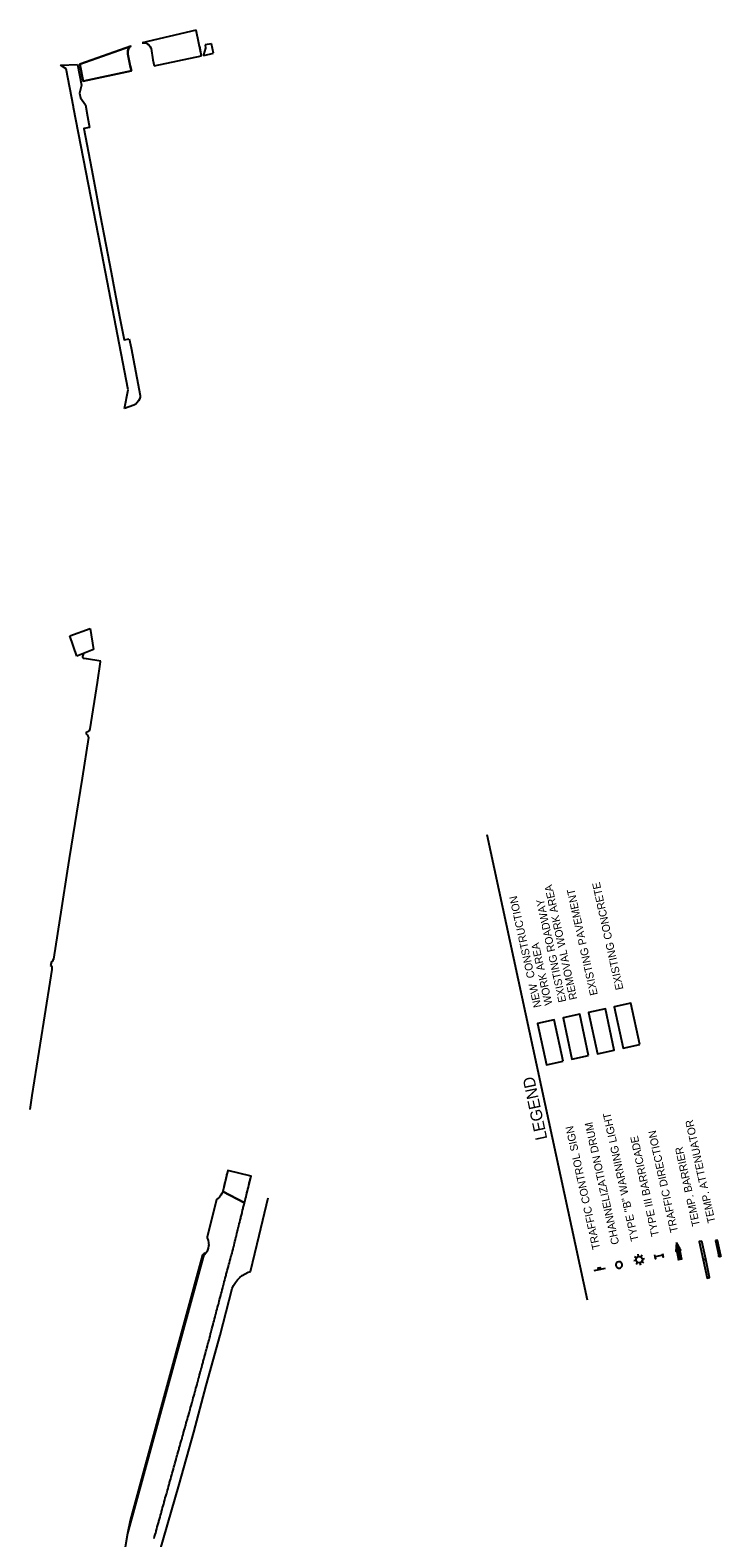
# Model space of a CAD drawing. Extents: x 1795987 to 1799689, y 243690 to 251545.
# Drawn here: x 1798998 to 1799689, y 250036 to 251545 of the extents above; entities that cross this region are included whole.
import ezdxf

# ---------------------------------------------------------------- set-up
doc = ezdxf.new("R2010")
doc.units = 0
for name, color, linetype in [('EP', 7, 'Continuous'), ('LEGEND', 7, 'Continuous'), ('Level 23', 7, 'Continuous'), ('Level 30', 7, 'Continuous'), ('Level 62', 7, 'Continuous')]:
    doc.layers.add(name, color=color, linetype=linetype)

# ---------------------------------------------------------------- blocks, each defined once
blk = doc.blocks.new('T21LR')
at = {"layer": 'Level 23'}
for p, q in [((0, 2), (31.5, 2)), ((0, -2), (31.5, -2))]:
    blk.add_line(p, q, dxfattribs=at)
blk.add_lwpolyline([(0, -2), (4, -2), (4, 2), (0, 2)], close=True, dxfattribs=at)
blk.add_circle((31.5, 0), 2, dxfattribs=at)

msp = doc.modelspace()

# ---------------------------------------------------------------- linework, layer by layer
at = {"layer": 'EP'}
for p, q in [((1799167.6, 251528.7), (1799169.5, 251519)), ((1799179.8, 251531.2), (1799173.2, 251529.9)), ((1799028.5, 251509.8), (1799045.8, 251510.4)), ((1799059.6, 251406.2), (1799063.9, 251383.2)), ((1799092.6, 251166.3), (1799096.4, 251184.9)), ((1799065.5, 250892), (1799068.8, 250912.7)), ((1799068.9, 250913.4), (1799069, 250913.4)), ((1799035.8, 250703.5), (1799037.8, 250715.9)), ((1799019.6, 250612.8), (1799018.8, 250608.9)), ((1798998.3, 250465.1), (1799000.3, 250479.1))]:
    msp.add_line(p, q, dxfattribs=at)
for points in [[(1799041.6, 251468.2), (1799034.2, 251506.1), (1799028.5, 251509.8)], [(1799045.8, 251510.4), (1799049.6, 251489.8), (1799047.5, 251481.7), (1799048.6, 251476.9), (1799053.5, 251469.9), (1799055.6, 251458.3), (1799057.7, 251447.2)], [(1799096.4, 251184.9), (1799066.7, 251339), (1799041.8, 251467.3), (1799041.6, 251468.2)], [(1799057.7, 251447.2), (1799052, 251446.2), (1799059.6, 251406.2)], [(1799063.9, 251383.2), (1799068.4, 251359.7), (1799074, 251330.3), (1799079.3, 251302.7), (1799082.7, 251284.5), (1799088, 251256.7), (1799092.2, 251234.9), (1799097.5, 251235.9)], [(1799097.5, 251235.9), (1799099.3, 251226.8), (1799108.4, 251179.3), (1799108.2, 251177.7), (1799107.6, 251175.7), (1799106.7, 251173.8), (1799105.4, 251172.1), (1799103.9, 251170.6), (1799102.1, 251169.5), (1799092.6, 251166.3)], [(1799069, 250913.4), (1799054.5, 250915.7), (1799052.2, 250916.1), (1799051.7, 250916.3), (1799051.5, 250916.5), (1799051.3, 250916.8), (1799051.1, 250917.6), (1799051.1, 250918.2), (1799051.2, 250919.3), (1799051.9, 250921.1)], [(1799068.8, 250912.7), (1799068.9, 250913.4)], [(1799037.8, 250715.9), (1799050.5, 250796.5), (1799056.9, 250837.1), (1799056.4, 250838.4), (1799055.6, 250839.6), (1799055.4, 250839.8), (1799055.3, 250839.9), (1799054.7, 250840.5), (1799054.5, 250841.3), (1799054.6, 250842.1), (1799055.1, 250842.7), (1799055.9, 250843), (1799056.1, 250843), (1799056.2, 250843), (1799057.2, 250843.8), (1799058, 250844.8), (1799058.3, 250845.8), (1799065.5, 250892)], [(1799019.6, 250612.8), (1799020.7, 250613.4), (1799021.4, 250614.3), (1799021.8, 250615.4), (1799021.9, 250615.5), (1799029.9, 250666.7), (1799035.8, 250703.5)], [(1799000.3, 250479.1), (1799012, 250552.2), (1799020.3, 250605.1), (1799020.4, 250606.2), (1799020.2, 250607.3), (1799019.6, 250608.3), (1799018.8, 250608.9)], [(1799122.3, 250035.8), (1799122.8, 250037.8), (1799123.4, 250039.7), (1799123.9, 250041.6), (1799124.3, 250042.9), (1799124.4, 250043.6), (1799125, 250045.5), (1799125.5, 250047.4), (1799126, 250049.3), (1799126.6, 250051.3), (1799126.9, 250052.6), (1799127.1, 250053.2), (1799127.6, 250055.1), (1799128.2, 250057), (1799128.7, 250059), (1799129.2, 250060.9), (1799129.6, 250062.2), (1799129.8, 250062.8), (1799130.3, 250064.8), (1799130.8, 250066.7), (1799131.4, 250068.6), (1799131.9, 250070.5), (1799132.3, 250071.9), (1799132.5, 250072.5), (1799133, 250074.4), (1799133.5, 250076.3), (1799134.1, 250078.2), (1799134.6, 250080.2), (1799135, 250081.5), (1799135.2, 250082.1), (1799135.7, 250084), (1799136.2, 250085.9), (1799136.8, 250087.9), (1799137.3, 250089.8), (1799137.7, 250091.1), (1799137.8, 250091.7), (1799138.4, 250093.7), (1799138.9, 250095.6), (1799139.5, 250097.5), (1799140, 250099.4), (1799140.4, 250101), (1799141.1, 250103.3), (1799141.6, 250105.2), (1799141.8, 250105.8), (1799142.1, 250107.1), (1799142.7, 250109.1), (1799143.1, 250110.6), (1799143.8, 250112.9), (1799144.3, 250114.8), (1799144.5, 250115.4), (1799144.8, 250116.8), (1799145.4, 250118.7), (1799145.8, 250120.3), (1799146.5, 250122.5), (1799147, 250124.5), (1799147.2, 250125.1), (1799147.5, 250126.4), (1799148.1, 250128.3), (1799148.5, 250129.9), (1799149.1, 250132.2), (1799149.7, 250134.1), (1799149.9, 250134.7), (1799150.2, 250136), (1799150.8, 250138), (1799151.2, 250139.5), (1799151.8, 250141.8), (1799152.4, 250143.7), (1799152.5, 250144.3), (1799152.9, 250145.7), (1799153.5, 250147.6), (1799153.9, 250149.1), (1799154.5, 250151.4), (1799155.1, 250153.4), (1799155.2, 250154), (1799155.6, 250155.3), (1799156.1, 250157.2), (1799156.6, 250158.8), (1799157.2, 250161.1), (1799157.8, 250163), (1799157.9, 250163.6), (1799158.3, 250164.9), (1799158.8, 250166.8), (1799159.3, 250168.4), (1799159.9, 250170.7), (1799160.4, 250172.6), (1799160.6, 250173.2), (1799161, 250174.6), (1799161.5, 250176.5), (1799161.9, 250178.1), (1799162.6, 250180.3), (1799163.1, 250182.3), (1799163.3, 250182.9), (1799163.6, 250184.2), (1799164.1, 250186.1), (1799164.6, 250187.7), (1799165.2, 250190), (1799165.7, 250191.9), (1799165.9, 250192.5), (1799166.3, 250193.8), (1799166.8, 250195.8), (1799167.2, 250197.3), (1799167.8, 250199.6), (1799168.4, 250201.6), (1799168.5, 250202.2), (1799168.9, 250203.5), (1799169.4, 250205.4), (1799169.9, 250207), (1799170.5, 250209.3), (1799171, 250211.2), (1799171.2, 250211.8), (1799171.5, 250213.1), (1799172, 250215.1), (1799172.5, 250216.6), (1799173.1, 250218.9), (1799173.6, 250220.9), (1799173.7, 250221.5), (1799174.1, 250222.8), (1799174.6, 250224.7), (1799175, 250226.3), (1799175.6, 250228.6), (1799176.1, 250230.5), (1799176.3, 250231.1), (1799176.6, 250232.5), (1799177.2, 250234.4), (1799177.6, 250236), (1799178.2, 250238.3), (1799178.7, 250240.2), (1799178.8, 250240.8), (1799179.2, 250242.1), (1799179.7, 250244.1), (1799180.1, 250245.6), (1799180.7, 250247.9), (1799181.2, 250249.9), (1799181.4, 250250.5), (1799181.8, 250251.8), (1799182.3, 250253.7), (1799182.7, 250255.4), (1799183.3, 250257.6), (1799183.8, 250259.5), (1799184, 250260.3), (1799184.3, 250261.5), (1799184.8, 250263.4), (1799185.3, 250265.1), (1799185.8, 250267.3), (1799186.4, 250269.2), (1799186.6, 250269.9), (1799186.9, 250271.1), (1799187.4, 250273.1), (1799187.8, 250274.8), (1799188.4, 250276.9), (1799188.9, 250278.9), (1799189.1, 250279.6), (1799189.4, 250280.8), (1799189.9, 250282.7), (1799190.4, 250284.4), (1799191, 250286.6), (1799191.5, 250288.5), (1799191.7, 250289.3), (1799192, 250290.5), (1799192.5, 250292.4), (1799192.9, 250294.1), (1799193.5, 250296.3), (1799194, 250298.2), (1799194.2, 250298.9), (1799194.5, 250300.1), (1799195.1, 250302.1), (1799195.5, 250303.8), (1799196.1, 250305.9), (1799196.6, 250307.9), (1799196.8, 250308.6), (1799197.1, 250309.8), (1799197.6, 250311.7), (1799198.1, 250313.4), (1799198.6, 250315.6), (1799199.1, 250317.5), (1799199.3, 250318.3), (1799199.7, 250319.5), (1799200.2, 250321.4), (1799200.6, 250323.1), (1799201.2, 250325.3), (1799201.7, 250327.2), (1799201.9, 250327.9), (1799202.2, 250329.2), (1799202.7, 250331.1), (1799203.1, 250332.8), (1799203.6, 250335), (1799204.1, 250336.9), (1799204.3, 250337.6), (1799204.6, 250338.9), (1799205.1, 250340.8), (1799205.5, 250342.5), (1799206, 250344.7), (1799206.5, 250346.6), (1799206.7, 250347.4), (1799207, 250348.6), (1799207.5, 250350.5), (1799207.9, 250352.2), (1799208.4, 250354.4), (1799208.9, 250356.3), (1799209.1, 250357.1), (1799209.4, 250358.3), (1799209.9, 250360.2), (1799210.3, 250361.9), (1799210.8, 250364.1), (1799211.3, 250366), (1799211.5, 250366.8), (1799211.8, 250368), (1799212.3, 250369.9), (1799212.7, 250371.6), (1799219.3, 250398.3), (1799196, 250404), (1799190.9, 250382.9), (1799190.1, 250380.9), (1799189, 250379.1), (1799188.3, 250378.2), (1799187.6, 250377.4), (1799186, 250375.8), (1799184.6, 250374.8), (1799175.2, 250337.4), (1799175.5, 250336.7), (1799176.4, 250333.9), (1799176.8, 250332), (1799176.8, 250331), (1799176.9, 250329.6), (1799176.8, 250328.5), (1799176.3, 250326.3), (1799175.6, 250324.2), (1799174.9, 250322.7), (1799173.1, 250319.9), (1799173.2, 250321.4), (1799172.5, 250320.9), (1799095.7, 250040.7), (1799091, 250013.3)], [(1799218.6, 250302.9), (1799227.2, 250339), (1799236.5, 250376.7)], [(1799124, 250009.1), (1799147.2, 250089.9), (1799161.9, 250142), (1799174.5, 250188.9), (1799188.2, 250239.3), (1799200.5, 250285.8), (1799201.8, 250288.9), (1799203.6, 250291.8), (1799205.6, 250294.4), (1799207.9, 250296.8), (1799210.5, 250298.9), (1799213.4, 250300.7), (1799216.4, 250302.1), (1799218.6, 250302.9)]]:
    msp.add_lwpolyline(points, dxfattribs=at)
at = {"layer": 'LEGEND'}
for p, q in [((1799555.6, 250274.2), (1799455.4, 250739.6)), ((1799606.8, 250317.8), (1799606.3, 250320.1)), ((1799644.9, 250332), (1799644.2, 250323)), ((1799644.2, 250323), (1799645.1, 250323.2)), ((1799649.1, 250324), (1799644.9, 250332)), ((1799645.1, 250323.2), (1799646.9, 250314.3)), ((1799648.2, 250323.8), (1799649.1, 250324)), ((1799650, 250314.9), (1799648.2, 250323.8)), ((1799573.5, 250306), (1799562.1, 250303.5)), ((1799604.3, 250314), (1799602.1, 250313.6)), ((1799604.8, 250316.5), (1799602.8, 250317.7)), ((1799604.5, 250310.1), (1799605.7, 250312)), ((1799608.1, 250311.6), (1799608.6, 250309.3)), ((1799610.4, 250319.3), (1799609.2, 250317.4)), ((1799612.1, 250311.7), (1799610.1, 250313)), ((1799610.6, 250315.4), (1799612.8, 250315.9))]:
    msp.add_line(p, q, dxfattribs=at)
for points in [[(1799582.5, 250524.4), (1799573.6, 250565.7), (1799556.9, 250562.1), (1799565.8, 250520.8)], [(1799608.1, 250529.9), (1799599.2, 250571.2), (1799582.5, 250567.7), (1799591.4, 250526.3)], [(1799531.3, 250513.4), (1799522.4, 250554.7), (1799505.7, 250551.1), (1799514.7, 250509.8)], [(1799556.9, 250518.9), (1799548, 250560.2), (1799531.3, 250556.6), (1799540.2, 250515.3)], [(1799670, 250333.4), (1799667.6, 250332.9), (1799671.5, 250314.6), (1799674, 250315.1)], [(1799566.9, 250304.6), (1799566.5, 250306.5), (1799568.4, 250306.9), (1799568.8, 250305)], [(1799674, 250315.1), (1799671.5, 250314.6), (1799675.5, 250296.2), (1799677.9, 250296.8)]]:
    msp.add_lwpolyline(points, close=True, dxfattribs=at)
for points in [[(1799630.7, 250321), (1799631.4, 250317.2), (1799631, 250319.1), (1799623.4, 250317.6), (1799623.8, 250315.7), (1799623, 250319.5)], [(1799644.2, 250323.2), (1799644.3, 250323)], [(1799644.3, 250324.1), (1799644.5, 250323)], [(1799644.4, 250326), (1799645, 250323.1)], [(1799644.4, 250325.1), (1799644.8, 250323.1)], [(1799644.5, 250326.9), (1799647.1, 250314.3)], [(1799644.6, 250327.9), (1799647.3, 250314.3)], [(1799644.7, 250328.8), (1799647.6, 250314.4)], [(1799644.8, 250330.7), (1799648.1, 250314.5)], [(1799644.8, 250329.7), (1799647.8, 250314.4)], [(1799644.9, 250331.6), (1799648.3, 250314.5)], [(1799645.2, 250331.4), (1799648.6, 250314.6)], [(1799645.6, 250330.6), (1799648.9, 250314.7)], [(1799646.1, 250329.8), (1799649.1, 250314.7)], [(1799646.5, 250328.9), (1799649.4, 250314.8)], [(1799646.9, 250328.1), (1799649.6, 250314.8)], [(1799647.4, 250327.3), (1799649.9, 250314.9)], [(1799647.8, 250326.5), (1799648.3, 250323.8)], [(1799648.2, 250325.6), (1799648.6, 250323.9)], [(1799648.7, 250324.8), (1799648.8, 250323.9)]]:
    msp.add_lwpolyline(points, dxfattribs=at)
msp.add_circle((1799607.5, 250314.7), 3.19, dxfattribs=at)
for start, end in [(102.1577, 282.1577), (282.1577, 102.1577)]:
    msp.add_arc((1799587.3, 250309.5), 3.18, start, end, dxfattribs=at)
at = {"layer": 'Level 30'}
for p, q in [((1799179.8, 251531.2), (1799173.2, 251529.9)), ((1799181.6, 251521.6), (1799179.8, 251531.2))]:
    msp.add_line(p, q, dxfattribs=at)
msp.add_lwpolyline([(1799173.2, 251529.9), (1799173.8, 251526.6), (1799171.8, 251520.1), (1799171.9, 251519.5), (1799181.6, 251521.6)], dxfattribs=at)
at = {"layer": 'Level 62'}
for p, q in [((1799164.2, 251544.8), (1799110.4, 251532.2)), ((1799048.1, 251510.8), (1799099, 251528.6)), ((1799122.4, 251508.9), (1799169.6, 251519)), ((1799038, 250938.8), (1799058.2, 250946.1)), ((1799045, 250918.4), (1799038, 250938.8)), ((1799058.2, 250946.1), (1799061.5, 250925)), ((1799061.5, 250925), (1799045, 250918.4)), ((1799190.9, 250382.9), (1799212.7, 250371.6)), ((1799173.2, 250321.4), (1799173.1, 250319.9))]:
    msp.add_line(p, q, dxfattribs=at)
for points in [[(1799169.6, 251519), (1799167, 251531.6), (1799164.2, 251544.8)], [(1799099.7, 251504), (1799098.5, 251508.9), (1799096, 251520.7), (1799095.9, 251522.5), (1799096.1, 251524.2), (1799096.7, 251525.9), (1799097.7, 251527.4), (1799099, 251528.6), (1799048.1, 251510.8), (1799051.3, 251493.6), (1799099.7, 251504)], [(1799099, 251528.6), (1799097.7, 251527.4), (1799096.7, 251525.9), (1799096.1, 251524.2), (1799095.9, 251522.5), (1799096, 251520.7), (1799098.5, 251508.9), (1799099.7, 251504)], [(1799110.4, 251532.2), (1799112.2, 251532.2), (1799113.9, 251531.9), (1799115.5, 251531.2), (1799117, 251530.1), (1799118.1, 251528.8), (1799118.9, 251527.2), (1799119.2, 251526.3), (1799121.1, 251515.2), (1799122.4, 251508.9)], [(1799099.7, 251504), (1799051.3, 251493.6), (1799048.1, 251510.8)], [(1799565.8, 250520.8), (1799582.5, 250524.4), (1799573.6, 250565.7), (1799556.9, 250562.1), (1799565.8, 250520.8)], [(1799219, 250397.1), (1799219.3, 250398.3), (1799196, 250404), (1799195.6, 250402.5), (1799195.2, 250401.2), (1799195.1, 250400.5), (1799194.8, 250399.5), (1799194.6, 250398.6), (1799194.2, 250396.9), (1799194.1, 250396.7), (1799193.9, 250395.8), (1799193.7, 250394.7), (1799193.6, 250394.4), (1799193.2, 250392.8), (1799193.2, 250392.8), (1799192.7, 250390.8), (1799192.7, 250390.7), (1799192.2, 250388.9), (1799192.1, 250387.9), (1799192, 250387.4), (1799191.4, 250384.3), (1799190.9, 250382.9), (1799212.7, 250371.6), (1799212.7, 250371.9), (1799213.2, 250373.8), (1799213.7, 250375.8), (1799213.9, 250376.5), (1799214.2, 250377.7), (1799214.7, 250379.6), (1799215.1, 250381.3), (1799215.1, 250381.6), (1799215.6, 250383.5), (1799216.1, 250385.5), (1799216.3, 250386.2), (1799216.6, 250387.4), (1799217.1, 250389.3), (1799217.5, 250391), (1799217.5, 250391.3), (1799218, 250393.2), (1799218.2, 250394.1), (1799218.5, 250395.2), (1799218.7, 250395.9), (1799219, 250397.1)], [(1799122.3, 250035.8), (1799122.8, 250037.8), (1799123.4, 250039.7), (1799123.9, 250041.6), (1799124.3, 250042.9), (1799124.4, 250043.6), (1799125, 250045.5), (1799125.5, 250047.4), (1799126, 250049.3), (1799126.6, 250051.3), (1799126.9, 250052.6), (1799127.1, 250053.2), (1799127.6, 250055.1), (1799128.2, 250057), (1799128.7, 250059), (1799129.2, 250060.9), (1799129.6, 250062.2), (1799129.8, 250062.8), (1799130.3, 250064.8), (1799130.8, 250066.7), (1799131.4, 250068.6), (1799131.9, 250070.5), (1799132.3, 250071.9), (1799132.5, 250072.5), (1799133, 250074.4), (1799133.5, 250076.3), (1799134.1, 250078.2), (1799134.6, 250080.2), (1799135, 250081.5), (1799135.2, 250082.1), (1799135.7, 250084), (1799136.2, 250085.9), (1799136.8, 250087.9), (1799137.3, 250089.8), (1799137.7, 250091.1), (1799137.8, 250091.7), (1799138.4, 250093.7), (1799138.9, 250095.6), (1799139.5, 250097.5), (1799140, 250099.4), (1799140.4, 250101), (1799141.1, 250103.3), (1799141.6, 250105.2), (1799141.8, 250105.8), (1799142.1, 250107.1), (1799142.7, 250109.1), (1799143.1, 250110.6), (1799143.8, 250112.9), (1799144.3, 250114.8), (1799144.5, 250115.4), (1799144.8, 250116.8), (1799145.4, 250118.7), (1799145.8, 250120.3), (1799146.5, 250122.5), (1799147, 250124.5), (1799147.2, 250125.1), (1799147.5, 250126.4), (1799148.1, 250128.3), (1799148.5, 250129.9), (1799149.1, 250132.2), (1799149.7, 250134.1), (1799149.9, 250134.7), (1799150.2, 250136), (1799150.8, 250138), (1799151.2, 250139.5), (1799151.8, 250141.8), (1799152.4, 250143.7), (1799152.5, 250144.3), (1799152.9, 250145.7), (1799153.5, 250147.6), (1799153.9, 250149.1), (1799154.5, 250151.4), (1799155.1, 250153.4), (1799155.2, 250154), (1799155.6, 250155.3), (1799156.1, 250157.2), (1799156.6, 250158.8), (1799157.2, 250161.1), (1799157.8, 250163), (1799157.9, 250163.6), (1799158.3, 250164.9), (1799158.8, 250166.8), (1799159.3, 250168.4), (1799159.9, 250170.7), (1799160.4, 250172.6), (1799160.6, 250173.2), (1799161, 250174.6), (1799161.5, 250176.5), (1799161.9, 250178.1), (1799162.6, 250180.3), (1799163.1, 250182.3), (1799163.3, 250182.9), (1799163.6, 250184.2), (1799164.1, 250186.1), (1799164.6, 250187.7), (1799165.2, 250190), (1799165.7, 250191.9), (1799165.9, 250192.5), (1799166.3, 250193.8), (1799166.8, 250195.8), (1799167.2, 250197.3), (1799167.8, 250199.6), (1799168.4, 250201.6), (1799168.5, 250202.2), (1799168.9, 250203.5), (1799169.4, 250205.4), (1799169.9, 250207), (1799170.5, 250209.3), (1799171, 250211.2), (1799171.2, 250211.8), (1799171.5, 250213.1), (1799172, 250215.1), (1799172.5, 250216.6), (1799173.1, 250218.9), (1799173.6, 250220.9), (1799173.7, 250221.5), (1799174.1, 250222.8), (1799174.6, 250224.7), (1799175, 250226.3), (1799175.6, 250228.6), (1799176.1, 250230.5), (1799176.3, 250231.1), (1799176.6, 250232.5), (1799177.2, 250234.4), (1799177.6, 250236), (1799178.2, 250238.3), (1799178.7, 250240.2), (1799178.8, 250240.8), (1799179.2, 250242.1), (1799179.7, 250244.1), (1799180.1, 250245.6), (1799180.7, 250247.9), (1799181.2, 250249.9), (1799181.4, 250250.5), (1799181.8, 250251.8), (1799182.3, 250253.7), (1799182.7, 250255.4), (1799183.3, 250257.6), (1799183.8, 250259.5), (1799184, 250260.3), (1799184.3, 250261.5), (1799184.8, 250263.4), (1799185.3, 250265.1), (1799185.8, 250267.3), (1799186.4, 250269.2), (1799186.6, 250269.9), (1799186.9, 250271.1), (1799187.4, 250273.1), (1799187.8, 250274.8), (1799188.4, 250276.9), (1799188.9, 250278.9), (1799189.1, 250279.6), (1799189.4, 250280.8), (1799189.9, 250282.7), (1799190.4, 250284.4), (1799191, 250286.6), (1799191.5, 250288.5), (1799191.7, 250289.3), (1799192, 250290.5), (1799192.5, 250292.4), (1799192.9, 250294.1), (1799193.5, 250296.3), (1799194, 250298.2), (1799194.2, 250298.9), (1799194.5, 250300.1), (1799195.1, 250302.1), (1799195.5, 250303.8), (1799196.1, 250305.9), (1799196.6, 250307.9), (1799196.8, 250308.6), (1799197.1, 250309.8), (1799197.6, 250311.7), (1799198.1, 250313.4), (1799198.6, 250315.6), (1799199.1, 250317.5), (1799199.3, 250318.3), (1799199.7, 250319.5), (1799200.2, 250321.4), (1799200.6, 250323.1), (1799201.2, 250325.3), (1799201.7, 250327.2), (1799201.9, 250327.9), (1799202.2, 250329.2), (1799202.7, 250331.1), (1799203.1, 250332.8), (1799203.6, 250335), (1799204.1, 250336.9), (1799204.3, 250337.6), (1799204.6, 250338.9), (1799205.1, 250340.8), (1799205.5, 250342.5), (1799206, 250344.7), (1799206.5, 250346.6), (1799206.7, 250347.4), (1799207, 250348.6), (1799207.5, 250350.5), (1799207.9, 250352.2), (1799208.4, 250354.4), (1799208.9, 250356.3), (1799209.1, 250357.1), (1799209.4, 250358.3), (1799209.9, 250360.2), (1799210.3, 250361.9), (1799210.8, 250364.1), (1799211.3, 250366), (1799211.5, 250366.8), (1799211.8, 250368), (1799212.3, 250369.9), (1799212.7, 250371.6), (1799190.9, 250382.9), (1799190.1, 250380.9), (1799189, 250379.1), (1799188.3, 250378.2), (1799187.6, 250377.4), (1799186, 250375.8), (1799184.6, 250374.8), (1799175.2, 250337.4), (1799175.5, 250336.7), (1799176.4, 250333.9), (1799176.8, 250332), (1799176.8, 250331), (1799176.9, 250329.6), (1799176.8, 250328.5), (1799176.3, 250326.3), (1799175.6, 250324.2), (1799174.9, 250322.7), (1799173.1, 250319.9), (1799173.2, 250321.4), (1799172.5, 250320.9), (1799170.9, 250319.7), (1799170.7, 250319.4), (1799098.2, 250053.7), (1799095.7, 250040.7), (1799091, 250013.3)]]:
    msp.add_lwpolyline(points, dxfattribs=at)

# ---------------------------------------------------------------- block references
at = {"layer": 'LEGEND', "xscale": 0.5000000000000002, "yscale": 0.5000000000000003, "rotation": -77.69303510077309}
msp.add_blockref('T21LR', (1799684.6, 250334.1), dxfattribs=at)

# ---------------------------------------------------------------- texts
at = {"layer": 'LEGEND'}
for s, height, rotation, p in [('REMOVAL WORK AREA', 7.8, 102.4707, (1799545.6, 250575.6)), ('EXISTING PAVEMENT', 7.8, 102.4707, (1799566.1, 250580)), ('EXISTING CONCRETE', 7.8, 102.4707, (1799591.7, 250585.5)), ('NEW  CONSTRUCTION', 7.8, 102.4707, (1799509.7, 250567.8)), ('EXISTING ROADWAY', 7.8, 102.4707, (1799534.6, 250573.1)), ('WORK AREA', 7.8, 102.4707, (1799520.7, 250570.2)), ('LEGEND', 11.7, 101.9916, (1799515.6, 250435.7)), ('TYPE "B" WARNING LIGHT', 7.8, 102.4707, (1799607, 250334.1)), ('TRAFFIC CONTROL SIGN', 7.8, 102.4707, (1799568.5, 250325.8)), ('CHANNELIZATION DRUM', 7.8, 102.4707, (1799587.5, 250330.7)), ('TRAFFIC DIRECTION', 7.8, 102.4707, (1799646.4, 250342.8)), ('TEMP. ATTENUATOR', 7.8, 102.4707, (1799683.8, 250352.4)), ('TYPE III BARRICADE', 7.8, 101.9916, (1799627.4, 250338.8)), ('TEMP. BARRIER', 7.8, 102.4707, (1799668.3, 250349))]:
    msp.add_text(s, height=height, rotation=rotation, dxfattribs=at).set_placement(p)

doc.saveas('drawing.dxf')
